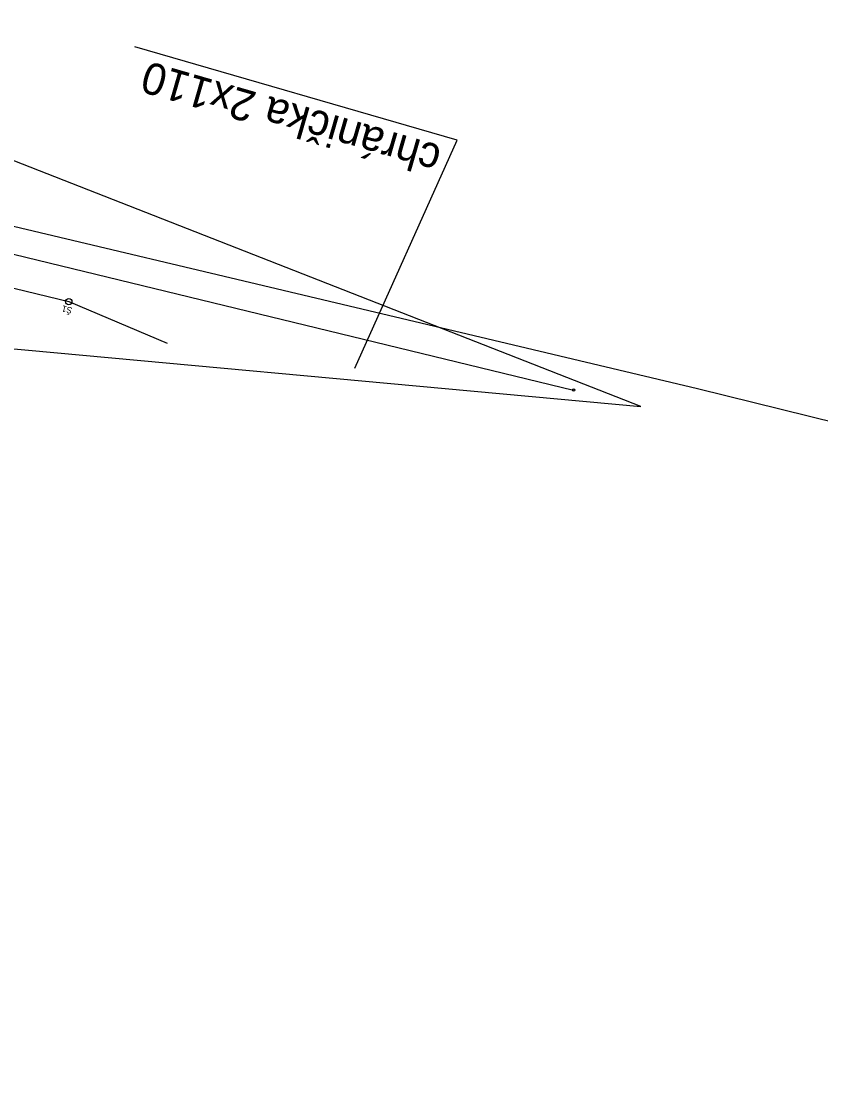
# Model space of a CAD drawing. Extents: x -748315 to -743169, y -1131781 to -1127091.
# Drawn here: x -747583.3 to -747520.1, y -1131774.4 to -1131689.9 of the extents above; entities that cross this region are included whole.
import ezdxf

# ---------------------------------------------------------------- set-up
doc = ezdxf.new("R2010")
doc.units = 0
for name, color, linetype in [('_ROZHLED_trojuhelník', 7, 'Continuous'), ('_Zabezpečovací zařízení_trasa', 7, 'Continuous'), ('Nový stav', 7, 'Continuous'), ('POP_KOLEJ', 7, 'Continuous'), ('SMEROVE_A_VYSKOVE_VYROVNANI', 7, 'Continuous'), ('TRATIVOD', 7, 'Continuous'), ('TRATIVOD_POP', 7, 'Continuous')]:
    doc.layers.add(name, color=color, linetype=linetype)

# ---------------------------------------------------------------- blocks, each defined once
blk = doc.blocks.new('AeccTickCircle')
blk.add_circle((0, 0), 0.5)

msp = doc.modelspace()

# ---------------------------------------------------------------- linework, layer by layer
at = {"layer": '_ROZHLED_trojuhelník'}
msp.add_lwpolyline([(-747594.358, -1131696.788), (-747654.001, -1131691.323), (-747593.974, -1131714.814), (-747534.332, -1131720.284)], close=True, dxfattribs=at)
at = {"layer": '_Zabezpečovací zařízení_trasa'}
msp.add_lwpolyline([(-747299.39, -1131774.358), (-747312.964, -1131771.536), (-747335.194, -1131765.862), (-747431.496, -1131743.033), (-747485.589, -1131729.823), (-747529.872, -1131718.897), (-747616.745, -1131698.315), (-747822.016, -1131648.41), (-747861.482, -1131639.038), (-748013.304, -1131601.999), (-748116.903, -1131577.077), (-748210.219, -1131554.485), (-748277.301, -1131538.228)], dxfattribs=at)
at = {"layer": 'Nový stav'}
for p, q in [((-747548.877, -1131699.252), (-747574.351, -1131691.884)), ((-747556.964, -1131717.267), (-747548.877, -1131699.252))]:
    msp.add_line(p, q, dxfattribs=at)
at = {"layer": 'SMEROVE_A_VYSKOVE_VYROVNANI'}
msp.add_lwpolyline([(-747586.682, -1131707.613), (-747539.653, -1131718.994)], dxfattribs=at)
at = {"layer": 'TRATIVOD'}
msp.add_lwpolyline([(-747602.124, -1131706.551), (-747591.472, -1131709.129), (-747579.575, -1131712.008), (-747571.785, -1131715.287)], dxfattribs=at)
msp.add_circle((-747579.575, -1131712.008), 0.25, dxfattribs=at)

# ---------------------------------------------------------------- block references
at = {"layer": 'POP_KOLEJ', "xscale": 0.2, "yscale": 0.19999999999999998, "rotation": -13.603869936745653}
msp.add_blockref('AeccTickCircle', (-747539.653, -1131718.994), dxfattribs=at)

# ---------------------------------------------------------------- texts
at = {"layer": 'Nový stav'}
msp.add_text('chránička 2x110', height=2.5, rotation=163.86678, dxfattribs=at).set_placement((-747549.973, -1131699.739))
at = {"layer": 'TRATIVOD_POP'}
msp.add_text('Š1', height=0.5, rotation=166, dxfattribs=at).set_placement((-747579.255, -1131712.497))

doc.saveas('drawing.dxf')
